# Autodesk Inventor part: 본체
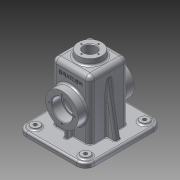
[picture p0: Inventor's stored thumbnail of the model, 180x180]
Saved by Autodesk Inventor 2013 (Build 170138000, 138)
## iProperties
Created: 2016-01
Part Number: 본체
Material: 알루미늄 6061
Document SubType Name: Modeling
Designer: User
Density: 2.71 g/cm^3
Mass: 806.269 g
Surface Area: 909.624 cm^2
Volume: 297.516 cm^3
Author: User
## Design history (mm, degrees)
sketch "스케치1"
  geometry: L1 (-32.5, -55)-(32.5, -55); L2 (32.5, -55)-(32.5, 55); L3 (32.5, 55)-(-32.5, 55); L4 (-32.5, 55)-(-32.5, -55); L5 (-32.5, -55)-(32.5, 55); L6 (32.5, -55)-(-32.5, 55); 1 further point
  constraints: 12 end point, 2 midpoint, 2 parallel, 1 horizontal, 1 perpendicular
  dimensions: "d0" = 65 distance of L2.end L3.end; "d2" = 110 distance of L1.end L2.end
extrude "돌출1" new body sketch "스케치1" stored distance "d3" = 65; taper "d4" = 0 deg
feature "쉘1" dims "d5" = 5
sketch "스케치2"
  geometry: L1 (-32.5, -55)-(-32.5, 55) reference; L2 (-32.5, 55)-(32.5, 55) reference; L3 (32.5, 55)-(32.5, -55) reference; L4 (32.5, -55)-(27.5, -55) reference; L5 (27.5, -55)-(27.5, 50) reference; L6 (27.5, 50)-(-27.5, 50) reference; L7 (-27.5, 50)-(-27.5, -55) reference; L8 (-27.5, -55)-(-32.5, -55) reference; L9 (32.5, 27.5)-(47.5, 27.5); L10 (47.5, 27.5)-(47.5, 0); L11 (75.884, 0)-(-75.884, 0); L12 (32.5, 27.5)-(32.5, 0); L13 (32.5, 0)-(47.5, 0); 2 further points
  constraints: 10 end point, 3 perpendicular, 2 midpoint, 2 point on line, 1 coincident, 1 parallel
  dimensions: "d6" = 55 diameter of L9 L11; "d8" = 15 distance of L9.start L9.end
revolve "회전1" sketch "스케치2" stored, may be unused: angle "d9" = 90 deg
hole "구멍1" diameter "d12" = 30; stored, may be unused: countersink angle "d16" = 90 deg, drill point angle "d18" = 118 deg; dims "d10" = 10, "d11" = 10, "d13" = 6, "d14" = 35, "d15" = 17, "d17" = 8
sketch "스케치3"
  geometry: L1 (84.363, 0)-(-84.363, 0); L2 (65, 20)-(55, 20); L3 (55, 20)-(55, 0); L4 (55, 0)-(65, 0); L5 (65, 0)-(65, 20); L6 (65, 20)-(55, 0); L7 (55, 20)-(65, 0); L8 (55, -32.5)-(-55, -32.5) reference; L9 (-55, -32.5)-(-55, -27.5) reference; L10 (-55, -27.5)-(50, -27.5) reference; L11 (50, -27.5)-(50, 27.5) reference; L12 (50, 27.5)-(-55, 27.5) reference; L13 (-55, 27.5)-(-55, 32.5) reference; L14 (-55, 32.5)-(55, 32.5) reference; L15 (55, 32.5)-(55, -32.5) reference; 3 further points
  constraints: 14 end point, 3 midpoint, 2 horizontal, 2 parallel, 1 coincident, 1 perpendicular, 1 point on line
  dimensions: "d19" = 40 diameter of L2 L1; "d21" = 10 distance between parallel lines of L15 L5; "d22" = 10 distance of L3.end L4.end
revolve "회전2" sketch "스케치3" stored, may be unused: angle "d23" = 90 deg
hole "구멍2" diameter "d26" = 21; stored, may be unused: countersink angle "d30" = 90 deg, drill point angle "d32" = 118 deg; dims "d24" = 10, "d25" = 10, "d27" = 6, "d28" = 4, "d29" = 2, "d31" = 8
sketch "스케치4"
  geometry: L1 (65, -65)-(65, 0) reference; L2 (0, 0)-(65, 0) reference; L3 (0, 0)-(0, -65) reference; L4 (65, -65)-(0, -65) reference; L5 (-27.5, -85)-(92.5, -85); L6 (92.5, -85)-(92.5, 20); L7 (92.5, 20)-(-27.5, 20); L8 (-27.5, 20)-(-27.5, -85); L9 (-27.5, -85)-(92.5, 20); L10 (92.5, -85)-(-27.5, 20); L11 (5, -60)-(60, -60); L12 (60, -60)-(60, -5); L13 (60, -5)-(5, -5); L14 (5, -5)-(5, -60); L15 (5, -60)-(60, -5); L16 (60, -60)-(5, -5); 1 further point
  constraints: 24 end point, 4 midpoint, 4 parallel, 2 horizontal, 2 perpendicular
  dimensions: "d33" = 120 distance of L6.end L7.end; "d35" = 105 distance of L5.end L6.end
extrude "돌출2" join sketch "스케치4" distance "d36" = 2; taper "d37" = 0 deg
sketch "스케치5"
  geometry: L1 (-32.5, -25)-(97.5, -25); L2 (97.5, -25)-(97.5, 90); L3 (97.5, 90)-(-32.5, 90); L4 (-32.5, 90)-(-32.5, -25); L5 (-32.5, -25)-(97.5, 90); L6 (97.5, -25)-(-32.5, 90); L7 (0, 0)-(65, 0); L8 (65, 0)-(65, 65); L9 (65, 65)-(0, 65); L10 (0, 65)-(0, 0); L11 (0, 0)-(65, 65); L12 (65, 0)-(0, 65); 1 further point
  constraints: 24 end point, 4 midpoint, 4 parallel, 2 horizontal, 2 perpendicular
  dimensions: "d38" = 130 distance of L3.end L2.end; "d39" = 115 distance of L2.end L1.end
extrude "돌출3" join sketch "스케치5" distance "d40" = 8; taper "d41" = 0 deg
sketch "스케치6"
  geometry: L1 (-42.5, -27.5)-(-42.5, -45); L2 (-27.5, 15)-(-30.5, 15) reference; L3 (-30.5, 15)-(-30.5, 17.5) reference; L4 (-30.5, 17.5)-(-47.5, 17.5) reference; L5 (-47.5, 17.5)-(-47.5, 27.5) reference; L6 (-47.5, 27.5)-(-32.5, 27.5) reference; L7 (-32.5, 27.5)-(-32.5, 55) reference; L8 (-32.5, 55)-(-20, 55) reference; L9 (-20, 55)-(-20, 65) reference; L10 (-20, 65)-(-10.5, 65) reference; L11 (-10.5, 65)-(-10.5, 50) reference; L12 (-10.5, 50)-(-27.5, 50) reference; L13 (-27.5, 50)-(-27.5, 15) reference; L14 (-30.5, -15)-(-27.5, -15) reference; L15 (-27.5, -15)-(-27.5, -55) reference; L16 (-27.5, -55)-(-60, -55) reference; L17 (-60, -55)-(-60, -53) reference; L18 (-60, -53)-(-65, -53) reference; L19 (-65, -53)-(-65, -45) reference; L20 (-65, -45)-(-32.5, -45) reference; L21 (-32.5, -45)-(-32.5, -27.5) reference; L22 (-32.5, -27.5)-(-47.5, -27.5) reference; L23 (-47.5, -27.5)-(-47.5, -17.5) reference; L24 (-47.5, -17.5)-(-30.5, -17.5) reference; L25 (-30.5, -17.5)-(-30.5, -15) reference; L26 (30.5, 15)-(27.5, 15) reference; L27 (27.5, 15)-(27.5, 50) reference; L28 (27.5, 50)-(10.5, 50) reference; L29 (10.5, 50)-(10.5, 65) reference; L30 (10.5, 65)-(20, 65) reference; L31 (20, 65)-(20, 55) reference; L32 (20, 55)-(32.5, 55) reference; L33 (32.5, 55)-(32.5, 27.5) reference; L34 (32.5, 27.5)-(47.5, 27.5) reference; L35 (47.5, 27.5)-(47.5, 17.5) reference; L36 (47.5, 17.5)-(30.5, 17.5) reference; L37 (30.5, 17.5)-(30.5, 15) reference; L38 (27.5, -15)-(30.5, -15) reference; L39 (30.5, -15)-(30.5, -17.5) reference; L40 (30.5, -17.5)-(47.5, -17.5) reference; L41 (47.5, -17.5)-(47.5, -27.5) reference; L42 (47.5, -27.5)-(32.5, -27.5) reference; L43 (32.5, -27.5)-(32.5, -45) reference; L44 (32.5, -45)-(65, -45) reference; L45 (65, -45)-(65, -53) reference; L46 (65, -53)-(60, -53) reference; L47 (60, -53)-(60, -55) reference; L48 (60, -55)-(27.5, -55) reference; L49 (27.5, -55)-(27.5, -15) reference; 1 further point
  constraints: 2 end point, 2 point on line, 1 parallel, 1 vertical
  dimensions: "d42" = 15 distance between parallel lines of L1 L15
feature "리브1" sketch "스케치6" dims "d43" = 1, "d44" = 6, "d45" = 0, "d46" = 0, "d47" = 1, "d48" = 1
sketch "스케치7"
  geometry: L1 (40.069, -32.5)-(-45, -47.5); L2 (-53, -57.5)-(-45, -57.5) reference; L3 (-45, -57.5)-(-45, 57.5) reference; L4 (-45, -32.5)-(55, -32.5) reference; 1 further point
  constraints: 2 end point, 2 point on line
  dimensions: "d49" = 10 distance from line of L2 L1.end; "d50" = 10 deg angle of L2 L1
feature "리브2" sketch "스케치7" dims "d51" = 1, "d52" = 10, "d53" = 0, "d54" = 0, "d55" = 1, "d56" = 1
sketch "스케치8"
  geometry: C1 r 7.5 at (-17.5, 75); 1 further point
  constraints: 1 centre point
  dimensions: "d57" = 15 diameter of C1; "d58" = 50 horizontal distance of point (32.5, 32.5) C1.centre; "d59" = 42.5 vertical distance of point (32.5, 32.5) C1.centre
extrude "돌출4" join sketch "스케치8" distance "d60" = 3; taper "d61" = 0 deg
sketch "스케치9"
  geometry: C1 r 7.5 at (0, 0) reference; C2 r 3 at (0, 0); 1 further point
  constraints: 1 centre point, 1 coincident
  dimensions: "d62" = 6 diameter of C2
extrude "돌출5" cut sketch "스케치9" distance "d64" = 40; taper "d65" = 0 deg
fillet "모깎기1" dims "d66" = 10
fillet "모깎기2" dims "d67" = 15
fillet "모깎기3" dims "d68" = 3
fillet "모깎기4" dims "d75" = 8
fillet "모깎기5" dims "d76" = 8
sketch "스케치10"
  geometry: C1 r 20 at (0, 0) reference; 1 further point
  constraints: 1 vertical alignment
  dimensions: "d77" = 14.5 distance of C1.centre point (0, 14.5)
hole "구멍3" sketch "스케치10" at (0, 14.5) diameter "d78" = 2.459; stored, may be unused: countersink angle "d82" = 90 deg, drill point angle "d84" = 118 deg; dims "d79" = 7, "d80" = 3.6, "d81" = 2, "d83" = 9
sketch "스케치11"
  geometry: C1 r 17.5 at (0, 0) reference; 1 further point
  constraints: 1 vertical alignment
  dimensions: "d88" = 21 distance of C1.centre point (0, 21)
hole "구멍4" sketch "스케치11" at (0, 21) diameter "d89" = 3.242; stored, may be unused: countersink angle "d93" = 90 deg, drill point angle "d95" = 118 deg; dims "d90" = 8, "d91" = 3.6, "d92" = 2, "d94" = 10
fillet "모깎기6" dims "d99" = 3
fillet "모깎기7" dims "d100" = 3
fillet "모깎기8" dims "d101" = 3
fillet "모깎기9" dims "d102" = 3
fillet "모깎기10" dims "d103" = 3
fillet "모깎기11" dims "d104" = 3
fillet "모깎기12" dims "d105" = 3
fillet "모깎기13" dims "d106" = 3
fillet "모깎기14" dims "d107" = 1
fillet "모깎기15" dims "d108" = 3
fillet "모깎기16" dims "d109" = 3
chamfer "모따기1" distance "d110" = 1; stored, may be unused: second distance "d111" = 2, angle "d112" = 45 deg
fillet "모깎기17" dims "d113" = 0.3
chamfer "모따기2" distance "d114" = 1; stored, may be unused: second distance "d115" = 2, angle "d116" = 45 deg
sketch "스케치12"
  geometry: L1 (44.5, 18)-(4.5, 18) reference; L2 (-8, 0)-(-8, -91) reference; 1 further point
  constraints: 1 other
  dimensions: "d117" = 26 distance from line of L1 point (24.5, -8); "d118" = 32.5 distance from line of L2 point (24.5, -8)
feature "엠보싱1" sketch "스케치12" dims "d6" = 55, "d8" = 15, "d119" = 0.5, "d120" = 0
feature "면 기울기1" dims angle "d121" = 5 deg
fillet "모깎기19" dims "d123" = 3
node "솔리드1"
mirror "대칭1"
mirror "대칭2"
mirror "대칭3"
pattern_linear "직사각형 패턴1" dims "d74" = 85
pattern_circular "원형 패턴1" dims angle "d86" = 360 deg
pattern_circular "원형 패턴2" dims angle "d97" = 360 deg
mirror "대칭4"
node "절단 모서리 투영1"
node "절단 모서리 투영2"
node "절단 모서리 투영3"
